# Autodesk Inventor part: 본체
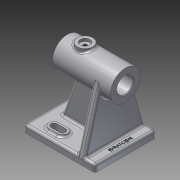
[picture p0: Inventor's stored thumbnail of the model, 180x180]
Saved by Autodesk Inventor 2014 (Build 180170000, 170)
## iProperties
Created: 2019-10
Part Number: 본체
Material: Aluminum 6061
Document SubType Name: Modeling
Designer: kh
Density: 2.71 g/cm^3
Appearance: Aluminum - Flat
Mass: 588.255 g
Surface Area: 541.061 cm^2
Volume: 217.068 cm^3
Author: kh
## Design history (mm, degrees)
sketch "Sketch1"
  geometry: L1 (0, 0)-(100, 0); L2 (100, 0)-(100, 86); L3 (100, 86)-(0, 86); L4 (0, 86)-(0, 0)
  constraints: 8 end point, 2 parallel, 1 horizontal, 1 perpendicular
  dimensions: "d0" = 100 distance of L2.end L3.end; "d1" = 86 distance of L1.end L2.end
extrude "Extrusion1" new body sketch "Sketch1" distance "d2" = 10; taper "d3" = 0 deg
workplane "Work Plane1"
sketch "Sketch3"
  geometry: L1 (100, 0)-(0, 0) reference; L2 (0, 0)-(0, 10) reference; L3 (100, 10)-(0, 10) reference; L4 (100, 0)-(100, 10) reference; L5 (18, 107)-(100, 107); L6 (100, 107)-(100, 86); L7 (100, 86)-(18, 86); L8 (18, 86)-(18, 107); L9 (18, 100.5)-(80, 100.5); L10 (80, 100.5)-(80, 86); L11 (80, 86)-(18, 86); L12 (18, 86)-(18, 100.5); L13 (80, 97.5)-(100, 97.5); L14 (100, 97.5)-(100, 86); L15 (100, 86)-(80, 86); L16 (80, 86)-(80, 97.5); 1 further point
  constraints: 24 end point, 6 parallel, 3 horizontal, 3 perpendicular, 3 point on line, 1 collinear
  dimensions: "d8" = 86 distance between parallel lines of L1 L7; "d9" = 82 distance of L5.start L5.end; "d11" = 42 diameter of L5 L7; "d12" = 23 diameter of L13 L15; "d13" = 29 diameter of L9 L7; "d14" = 62 distance between parallel lines of L16 L12
revolve "Revolution1" sketch "Sketch3" stored, may be unused: angle "d15" = 90 deg
workplane "Work Plane2"
sketch "Sketch4"
  geometry: L1 (18, 64)-(100, 64) reference; L2 (18, 22)-(100, 22) reference; L3 (18, 22)-(18, 64) reference; L4 (18, 43)-(43, 43); C1 r 11 at (43, 43); 1 further point
  constraints: 2 end point, 1 centre point, 1 midpoint, 1 perpendicular
  dimensions: "d17" = 22 diameter of C1; "d18" = 25 distance from line of L4.end L3
extrude "Extrusion2" join sketch "Sketch4" stored distance "d19" = 13; taper "d20" = 0 deg
hole "Hole1" diameter "d23" = 5.459; stored, may be unused: countersink angle "d27" = 90 deg, drill point angle "d29" = 118 deg; dims "d21" = 10, "d22" = 10, "d24" = 6, "d25" = 14, "d26" = 4, "d28" = 10
sketch "Sketch5" dims "d30" = 36
  geometry: L1 (0, 0)-(0, 18); C1 r 21 at (0, 0) reference; 5 further points
  constraints: 2 coincident, 2 end point, 1 vertical, 1 vertical alignment, 7 other
  dimensions: "d33" = 360 deg dimension on L1.start point (0, 18) (derived)
hole "Hole2" sketch "Sketch5" at (0, 18), (-18, 0), (0, -18), (18, 0) diameter "d35" = 2.459; stored, may be unused: countersink angle "d39" = 90 deg, drill point angle "d41" = 118 deg; dims "d36" = 8, "d37" = 14, "d38" = 4, "d40" = 10
sketch "Sketch6" dims "d42" = 36
  geometry: L1 (0, 0)-(0, 18); C1 r 21 at (0, 0) reference; 2 further points
  constraints: 2 coincident, 2 end point, 1 vertical, 1 vertical alignment, 2 other
hole "Hole3" sketch "Sketch6" at (0, 18) diameter "d43" = 2.459; stored, may be unused: countersink angle "d47" = 90 deg, drill point angle "d49" = 118 deg; dims "d44" = 8, "d45" = 14, "d46" = 4, "d48" = 10
pattern_circular "Circular Pattern1" dims angle "d51" = 360 deg
sketch "Sketch7"
  geometry: L1 (0, 0)-(100, 0) reference; L2 (0, 86)-(0, 0) reference; L3 (100, 86)-(0, 86) reference; L4 (100, 0)-(100, 86) reference; L5 (0, 43)-(100, 43); L6 (26, 70)-(38, 70); L7 (26, 63)-(38, 63); L8 (38, 77)-(26, 77); A1 r 7 centre (26, 70) between (26, 77) and (26, 63); A2 r 7 centre (38, 70) between (38, 63) and (38, 77); 2 further points
  constraints: 10 end point, 4 point on circle, 4 tangent, 3 midpoint, 2 centre point, 2 parallel
  dimensions: "d53" = 27 distance from line of L5 point (32, 70); "d54" = 12 distance of L6.end L6.start; "d55" = 7 radius of A2; "d56" = 26 distance from line of L2 L8.end
extrude "Extrusion3" join sketch "Sketch7" distance "d57" = 3; taper "d58" = 0 deg
sketch "Sketch8"
  geometry: L1 (38, 70)-(26, 70); L2 (38, 74.5)-(26, 74.5); L3 (26, 65.5)-(38, 65.5); A1 r 7 centre (38, 70) between (38, 63) and (38, 77) reference; A2 r 7 centre (26, 70) between (26, 77) and (26, 63) reference; A3 r 4.5 centre (38, 70) between (38, 65.5) and (38, 74.5); A4 r 4.5 centre (26, 70) between (26, 74.5) and (26, 65.5); 2 further points
  constraints: 8 end point, 4 point on circle, 4 tangent, 2 centre point, 1 horizontal, 1 midpoint, 1 parallel
  dimensions: "d59" = 9 diameter of A4
extrude "Extrusion4" cut sketch "Sketch8" stored distance "d60" = 3; taper "d61" = 0 deg
fillet "Fillet1" dims "d62" = 3
workplane "Work Plane4"
mirror "Mirror1"
fillet "Fillet2" dims "d63" = 3
fillet "Fillet3" dims "d64" = 3
workplane "Work Plane5"
sketch "Sketch9"
  geometry: L1 (0, -3)-(-7, -3) reference; L2 (-7, 83)-(0, 83) reference; L3 (-91.48, 19.728)-(-7.783, -2.896); L4 (-91.48, 60.272)-(-7.783, 82.896); L5 (-7.783, -2.896)-(-7.783, 82.896); A1 r 21 centre (-86, 40) between (-91.48, 19.728) and (-91.48, 60.272) reference; A2 r 3 centre (-7, 0) between (-10, 0) and (-7, -3) reference; A3 r 3 centre (-7, 80) between (-7, 83) and (-10, 80) reference; A4 r 21 centre (-86, 40) between (-91.48, 19.728) and (-91.48, 60.272)
  constraints: 6 end point, 6 point on circle, 4 tangent, 1 centre point, 1 coincident, 1 concentric, 1 perpendicular
extrude "Extrusion5" join sketch "Sketch9" distance "d66" = 10; taper "d67" = 0 deg
sketch "Sketch10"
  geometry: L1 (18, -107)-(100, -107) reference; L2 (0, 0)-(0, -7) reference; L3 (15, -10)-(35.018, -65); L4 (38, -10)-(48, -10) reference; L5 (3, -10)-(97, -10) reference; 1 further point
  constraints: 2 end point, 1 point on line
  dimensions: "d73" = 15 distance from line of L3.start L2; "d94" = 70 deg angle of L4 L3
sketch "Sketch11"
  geometry: L1 (100, 3)-(100, 83) reference; L2 (3, 0)-(97, 0) reference; L3 (0, 83)-(0, 3) reference; L4 (97, 86)-(3, 86) reference; L5 (38, 20.5)-(26, 20.5) reference; L6 (26, 11.5)-(38, 11.5) reference; L7 (26, 65.5)-(38, 65.5) reference; L8 (38, 74.5)-(26, 74.5) reference; L9 (90.732, 29.753)-(90.732, 56.247); L10 (90.732, 56.247)-(95.268, 56.247); L11 (95.268, 56.247)-(95.268, 29.753); L12 (95.268, 29.753)-(90.732, 29.753); L13 (95.268, 43)-(0, 43); L14 (93, 29.753)-(93, 56.247); A1 r 3 centre (97, 83) between (100, 83) and (97, 86) reference; A2 r 3 centre (97, 3) between (97, 0) and (100, 3) reference; A3 r 3 centre (3, 3) between (0, 3) and (3, 0) reference; A4 r 3 centre (3, 83) between (3, 86) and (0, 83) reference; A5 r 4.5 centre (38, 16) between (38, 11.5) and (38, 20.5) reference; A6 r 4.5 centre (26, 16) between (26, 20.5) and (26, 11.5) reference; A7 r 4.5 centre (26, 70) between (26, 74.5) and (26, 65.5) reference; A8 r 4.5 centre (38, 70) between (38, 65.5) and (38, 74.5) reference; 2 further points
  constraints: 4 end point, 4 midpoint, 1 perpendicular, 2 other
  dimensions: "d80" = 7 distance between parallel lines of L1 L14
emboss "Emboss1" sketch "Sketch11" dims "d0" = 100, "d1" = 86, "d8" = 86, "d9" = 82, "d11" = 42, "d12" = 23, "d13" = 29, "d14" = 62, "d81" = 0.5, "d82" = 0
chamfer "Chamfer1" distance "d84" = 1; stored, may be unused: second distance "d85" = 2, angle "d86" = 45 deg
chamfer "Chamfer2" distance "d87" = 1; stored, may be unused: second distance "d88" = 2, angle "d89" = 45 deg
fillet "Fillet11" dims "d92" = 3
feature "Rib1" dims "d95" = 1, "d96" = 10, "d97" = 0, "d98" = 0, "d99" = 1, "d100" = 1
fillet "Fillet18" dims "d106" = 3
fillet "Fillet19" dims "d107" = 3
fillet "Fillet20" dims "d108" = 3
fillet "Fillet21" dims "d109" = 3
body "Solid1"
node "Projected Loop2"
node "Projected Loop3"
node "Projected Loop4"
other parameters: "d65" = -15
